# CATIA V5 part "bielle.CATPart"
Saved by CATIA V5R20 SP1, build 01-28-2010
Part number: Part1.1.2.3.4.5
Bounding box of the stored display mesh (mm): x 55 to 87, y 0 to 30, z 28.093 to 41.907
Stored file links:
  E:\EDELI\gcausse\Edeli_2012_686_gcausse\bielle.CATPart
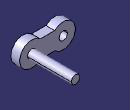
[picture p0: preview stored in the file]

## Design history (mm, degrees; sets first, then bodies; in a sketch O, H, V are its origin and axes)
Parameters
  long = 0.018
  diamtrou = 0.005
Body1 (main body)
  Sketch1 on zx-plane, origin (0, 0, 0), H (-1, 0, 0), V (0, 0, 1)
    line L1 (-66.899, 40) -> (-75.101, 40)
    line L2 (-66.899, 30) -> (-75.101, 30)
    arc A1 centre (-62, 35) radius 7 from (-66.899, 40) to (-66.899, 30) cw
    point P5 (-62, 35)
    point P6 (-57.101, 30)
    arc A2 centre (-80, 35) radius 7 from (-75.101, 40) to (-75.101, 30) ccw
    point P7 (-80, 35)
    circle A3 centre (-62, 35) radius 2.5
    distance P7 L1 = 5
    distance P5 L2 = 5
    distance L2 L1 = 10
    radius A1 = 7
    radius A2 = 7
    distance P5 P7 = 18 {= long}
    radius A3 = 2.5
    horizontal: L1 H, L2 H
    coincidence: A1 P6, P6 L2
  Pad1: profile Sketch1, direction (0, 1, 0), length 5
  Sketch2 on end face of Pad1, origin (0, 5, 0), H (-1, 0, 0), V (0, 0, 1)
    circle A1 centre (-80, 35) radius 2.5
    reference projected arc E1 centre (-80, 35) radius 7 from (-75.101, 40) to (-75.101, 30) ccw from edge [face of Pad1 from Sketch1.A2 | end face of Pad1]
    reference projected arc E2 centre (-80, 35) radius 7 from (-75.101, 40) to (-75.101, 30) ccw from edge [face of Pad1 from Sketch1.A2 | end face of Pad1]
    radius A1 = 2.5
    radius E2 = 7 (reference)
    concentricity: A1 E1
  Pad2: profile Sketch2, direction (0, 1, 0), length 25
